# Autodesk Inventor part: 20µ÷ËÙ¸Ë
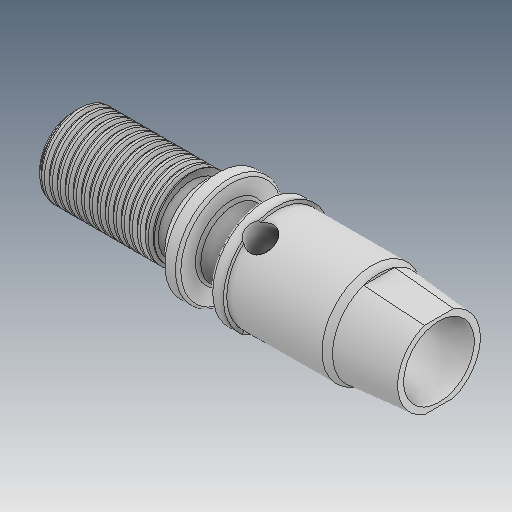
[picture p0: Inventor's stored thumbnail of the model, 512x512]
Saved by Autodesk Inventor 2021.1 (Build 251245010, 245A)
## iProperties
Created: 2019-05
Part Number: 20µ÷ËÙ¸Ë
Material: Ogólny
Document SubType Name: Modeling
Designer: user
Density: 1 g/cm^3
Appearance: Domyślna
Author: user
Revision Number: ÈÎºÎ
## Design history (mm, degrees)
feature "ÊäÈë1"
node "Bryła1"
